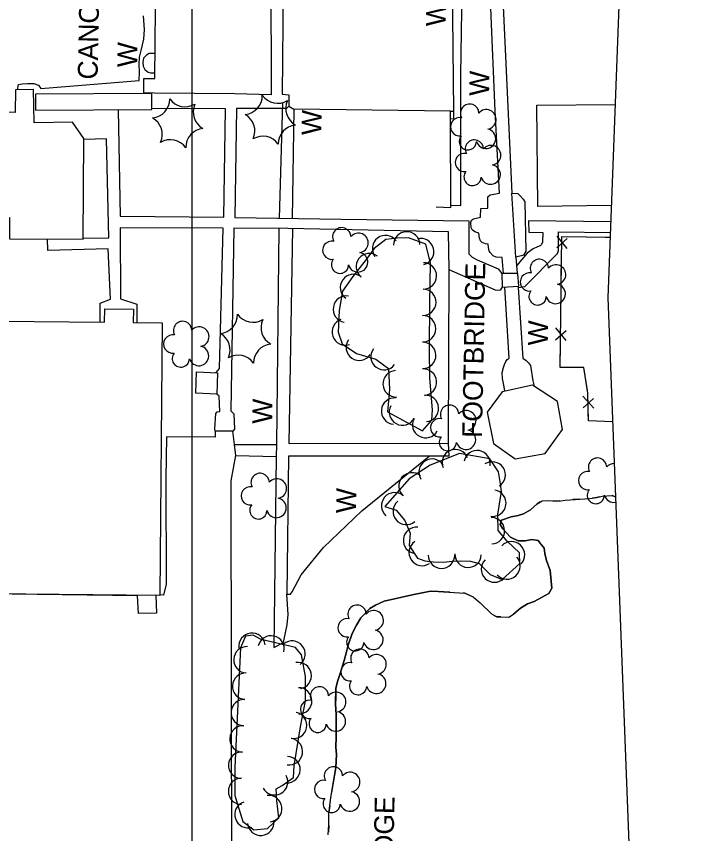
# Model space of a CAD drawing. Extents: x 591954 to 597000, y 198576 to 213500.
# Drawn here: x 594446.8 to 594650.3, y 209666.9 to 209914.5 of the extents above; entities that cross this region are included whole.
import ezdxf

# ---------------------------------------------------------------- set-up
doc = ezdxf.new("R2010")
doc.units = 0
for name, color, linetype in [('Level 10', 7, 'Continuous'), ('Level 12', 7, 'Continuous'), ('Level 15', 7, 'Continuous'), ('Level 17', 7, 'Continuous'), ('Level 18', 7, 'Continuous'), ('Level 19', 7, 'Continuous'), ('Level 4', 7, 'Continuous')]:
    doc.layers.add(name, color=color, linetype=linetype)

msp = doc.modelspace()

# ---------------------------------------------------------------- linework, layer by layer
at = {"layer": 'Level 10'}
for p, q in [((594500, 209500), (594500, 210500)), ((594500, 208500), (594500, 210000))]:
    msp.add_line(p, q, dxfattribs=at)
at = {"layer": 'Level 12'}
for points in [[(594513.34, 209927.19), (594523.83, 209927.08), (594523.89, 209890.77), (594512.94, 209890.99), (594488.59, 209891.26), (594485.34, 209891.3), (594485.39, 209895.68), (594488.65, 209895.65), (594489.01, 209927.47), (594513.34, 209927.19)], [(594446.43, 209885.39), (594405.52, 209885.59), (594405.47, 209874.71), (594398.11, 209874.75), (594398.08, 209869.64), (594405.35, 209869.61), (594405.27, 209853.82), (594444.7, 209853.63), (594444.67, 209847.16), (594466.99, 209847.05), (594467.15, 209877.52), (594463.75, 209882.48), (594452.14, 209882.29), (594451.97, 209892.38), (594446.47, 209892.29), (594446.43, 209885.39)], [(594452.58, 209886.09), (594487.76, 209886.31), (594487.73, 209891.11), (594452.55, 209890.89), (594452.58, 209886.09)], [(594604.29, 209887.62), (594628.02, 209887.85)], [(594626.86, 209857.17), (594604.58, 209856.96), (594604.29, 209887.62)], [(594430.68, 209822.33), (594473.47, 209821.92), (594473.51, 209825.91), (594482.17, 209825.83), (594482.13, 209821.78), (594490.93, 209821.69), (594490.14, 209739.13), (594429.23, 209739.72), (594429.13, 209729.13), (594406.41, 209729.35), (594406.8, 209769.83), (594396.44, 209769.93), (594396.53, 209779.02), (594382.62, 209779.15), (594382.6, 209777.29), (594353.34, 209777.57), (594353.77, 209822.05), (594381.3, 209821.78), (594381.34, 209825.57), (594391.73, 209825.47), (594391.68, 209819.76), (594430.65, 209819.38), (594430.68, 209822.33)], [(594507.4, 209800.08), (594501.06, 209800.34), (594501.32, 209806.82), (594507.66, 209806.57), (594507.4, 209800.08)], [(594610.57, 209797.83), (594602.96, 209802.78), (594593.79, 209800.77), (594589.26, 209794.58), (594591.22, 209785.09), (594597.77, 209780.48), (594606.88, 209782.05), (594612.06, 209789.37), (594610.57, 209797.83)]]:
    msp.add_lwpolyline(points, dxfattribs=at)
at = {"layer": 'Level 15'}
for p, q in [((594613.48, 209844.22), (594610.44, 209847.96)), ((594610.33, 209844.42), (594613.53, 209847.18)), ((594610.01, 209816.57), (594613.21, 209819.33)), ((594613.25, 209816.36), (594610.05, 209820.11)), ((594621.61, 209795.81), (594618.29, 209799.46)), ((594618.37, 209795.91), (594621.48, 209798.77))]:
    msp.add_line(p, q, dxfattribs=at)
for points in [[(594578.94, 209964.24), (594578.71, 209950.63), (594578.74, 209914.58), (594579.05, 209885.83), (594579.07, 209883.45), (594578.14, 209883.38)], [(594578.32, 209857.27), (594581.33, 209857.26), (594581.35, 209896.69), (594581.71, 209922.93), (594582.27, 209922.92), (594582.35, 209925.44), (594581.68, 209925.45), (594581.94, 209954.49), (594581.79, 209961.46)], [(594592.06, 209961.24), (594593.07, 209939.03), (594594.54, 209908.88), (594596.73, 209860.97), (594598.58, 209860.87), (594599.32, 209860.16), (594600.21, 209859.16), (594600.67, 209858.32), (594600.95, 209843.42), (594600.24, 209842.15), (594599.6, 209841.98), (594597.98, 209841.53), (594598.35, 209836.66)], [(594594.25, 209836.58), (594593.79, 209841.49), (594592.04, 209841.52), (594591.15, 209841.92), (594590.15, 209842.94), (594589.86, 209843.44), (594589.68, 209844.46), (594589.6, 209845.48), (594588.81, 209845.56), (594587.8, 209846.05), (594587.29, 209846.56), (594586.99, 209847.36), (594586.78, 209848.84), (594585.52, 209849.27), (594584.7, 209849.82), (594584.39, 209850.5), (594584.33, 209852.11), (594584.56, 209852.73), (594585.15, 209853.15), (594587.29, 209853.7), (594587.32, 209856.34), (594589.49, 209856.42), (594589.53, 209859.83), (594590.18, 209860.49), (594592.98, 209860.95), (594591.67, 209885.92), (594590.39, 209916.99)], [(594488.73, 209903.23), (594487.75, 209903.25), (594486.96, 209903.21), (594486.11, 209902.75), (594485.25, 209901.82), (594485.08, 209900.58), (594485.16, 209899.39), (594485.6, 209898.43), (594486.67, 209897.64), (594487.36, 209897.4), (594488.67, 209897.38)], [(594526.46, 209853.31), (594527.42, 209888.33)], [(594573.86, 209856.78), (594578.32, 209856.65), (594578.14, 209883.38), (594578.14, 209885.79), (594530.72, 209886.42), (594530.25, 209853.24)], [(594597.98, 209841.53), (594596.73, 209860.99)], [(594526.23, 209850.26), (594525.49, 209784.84), (594525.41, 209781.18), (594524.68, 209723.37)], [(594530.35, 209850.21), (594529.27, 209785.08), (594577.56, 209785.26), (594577.76, 209837.75)], [(594627.25, 209791.68), (594619.95, 209791.96), (594619.77, 209800.38), (594618.58, 209808.11), (594611.42, 209808.11), (594611.86, 209847.8), (594626.5, 209847.65)], [(594613.72, 209847.78), (594625.04, 209847.67)], [(594625.04, 209847.67), (594626.5, 209847.65)], [(594611.7, 209833.12), (594611.81, 209843.08)], [(594593.86, 209832.47), (594598.86, 209832.76), (594598.58, 209836.66), (594593.73, 209836.57), (594593.86, 209832.47)], [(594594.25, 209836.58), (594594.25, 209836.58)], [(594611.57, 209821.8), (594611.7, 209833.12)], [(594594.65, 209800.96), (594594.39, 209802.24), (594593.96, 209804.81), (594593.85, 209806.68), (594594.22, 209808.12), (594594.5, 209809.09), (594594.93, 209809.92), (594595.29, 209810.57), (594595.93, 209810.98), (594594.62, 209832.51)], [(594598.67, 209832.75), (594598.67, 209832.75)], [(594598.67, 209832.75), (594598.68, 209832.38), (594600.05, 209810.98), (594601.14, 209810.28), (594601.78, 209809.59), (594602.36, 209808.71), (594603.14, 209804.11), (594603.47, 209802.45)], [(594614.27, 209808.11), (594611.42, 209808.11), (594611.5, 209815.22)], [(594619.65, 209801.18), (594618.58, 209808.11), (594614.27, 209808.11)], [(594627.25, 209791.68), (594619.95, 209791.96), (594619.89, 209794.61)], [(594577.82, 209781.31), (594529.13, 209781.3), (594528.67, 209739.51), (594529.21, 209739.44), (594529.74, 209739.51), (594530.24, 209740.19), (594533, 209745.34), (594539.76, 209753.6), (594551.31, 209764.71), (594571.69, 209781.31)]]:
    msp.add_lwpolyline(points, dxfattribs=at)
at = {"layer": 'Level 17'}
for points in [[(594523.83, 209922.94), (594527.55, 209922.94), (594527.2, 209890.89), (594529.26, 209890.69), (594529.27, 209887.26), (594528.58, 209886.59), (594513.39, 209886.6), (594512.87, 209853.61), (594545.09, 209853.1), (594583.73, 209852.6), (594583.76, 209842.55), (594584.73, 209841.59), (594586.27, 209840.78), (594592.65, 209838.03), (594593.73, 209836.57)], [(594447.05, 209892.3), (594447.44, 209893.88), (594448.5, 209894.09), (594450.13, 209894.12), (594452.04, 209894.15), (594453.42, 209893.7), (594454.15, 209892.64), (594483.9, 209895.05), (594484, 209897.67), (594483.92, 209899.9), (594484.06, 209902.17), (594484.53, 209904.13), (594485.39, 209907.55), (594485.52, 209910.52), (594485.2, 209914.62)], [(594477.56, 209886.24), (594478.18, 209853.99), (594509.53, 209853.7), (594510.1, 209886.46), (594487.76, 209886.61)], [(594529.27, 209887.26), (594530.72, 209886.42)], [(594578.14, 209885.79), (594579.05, 209885.83)], [(594467, 209847.35), (594474.76, 209847.39), (594474.07, 209877.38), (594467.14, 209877.18)], [(594507.26, 209806.58), (594508.3, 209807.82), (594509.33, 209850.38), (594478.22, 209850.47), (594478.31, 209828.99), (594483.24, 209827.36)], [(594593.86, 209832.47), (594593.2, 209831.6), (594592.39, 209831.46), (594591.76, 209831.57), (594577.76, 209837.75), (594577.62, 209849.27), (594528.95, 209850.24), (594512.56, 209850.37), (594511.66, 209795.05), (594512.55, 209794.11), (594512.79, 209789.48), (594512.27, 209788.82)], [(594626.68, 209852.3), (594601.81, 209852.55), (594601.86, 209849.14), (594606.09, 209849.02), (594606.07, 209846.06), (594605.77, 209845.39), (594605.3, 209845.04), (594604.5, 209844.74), (594603.2, 209844.05), (594601.4, 209842.77), (594598.18, 209838.91)], [(594598.68, 209832.38), (594600.65, 209832.66), (594610.59, 209842.68), (594610.88, 209843.58), (594610.88, 209849.21), (594626.55, 209848.99)], [(594472.15, 209821.93), (594472.08, 209827.66), (594475.22, 209828.81), (594474.59, 209844.09), (594456.3, 209843.57), (594456.19, 209847.1)], [(594483.24, 209827.36), (594483.23, 209821.77)], [(594506.99, 209788.84), (594506.86, 209789.56), (594507.1, 209794.17), (594507.52, 209794.68), (594508.33, 209794.79), (594508.18, 209799.45), (594507.4, 209800.08)], [(594506.99, 209788.84), (594506.89, 209787.02), (594492.24, 209787.1), (594491.96, 209774.44), (594492.07, 209742.52), (594491.3, 209739.17), (594490.14, 209739.24)], [(594512.27, 209788.82), (594506.99, 209788.84)], [(594512.82, 209784.83), (594512.27, 209788.82)], [(594512.82, 209784.83), (594525.49, 209784.84)], [(594513.15, 209781.47), (594512.82, 209784.83)], [(594577.82, 209781.31), (594577.56, 209785.26)], [(594501.42, 209653.42), (594511.94, 209653.35), (594511.78, 209773.77), (594513.15, 209781.47)], [(594513.15, 209781.47), (594525.41, 209781.18)], [(594489.01, 209739.14), (594489.14, 209733.7), (594483.68, 209733.67), (594483.47, 209738.93), (594430.19, 209739.65), (594430.17, 209729.62), (594429.14, 209729.63)], [(594524.68, 209723.37), (594527.64, 209724.87), (594527.87, 209725.86), (594528.76, 209730.19), (594529.05, 209733.36), (594528.67, 209739.51)]]:
    msp.add_lwpolyline(points, dxfattribs=at)
at = {"layer": 'Level 18'}
for points in [[(594559.13, 209794.72), (594569.67, 209788.98), (594572.5, 209792.2), (594572.73, 209795.29), (594571.97, 209804.96), (594571.83, 209813.73), (594571.89, 209827.73), (594572.15, 209839.78), (594570.75, 209845.5), (594565.43, 209847.39), (594562.07, 209847.32), (594558.64, 209846.87), (594555.04, 209844.17), (594552.68, 209840.89), (594548.64, 209835.74), (594545.49, 209831.3), (594544.47, 209825.46), (594544.14, 209818.82), (594545.34, 209815.33), (594549.68, 209812.37), (594555.55, 209810.69), (594559.42, 209807.8), (594559.73, 209801.47), (594559.13, 209794.72)], [(594593.31, 209772.86), (594592.73, 209776.52), (594590.11, 209780.45), (594580.93, 209782.1), (594572, 209778.54), (594565.62, 209774.45), (594558.29, 209766.02), (594561.75, 209764.93), (594564.33, 209761.83), (594566.01, 209758), (594565.63, 209754.21)], [(594565.63, 209754.21), (594568.24, 209750.41), (594570.43, 209749.63), (594572.92, 209749.23), (594576.05, 209749.2), (594578.65, 209749.47), (594581.07, 209749.58), (594584.2, 209749.46), (594586.85, 209748.74), (594590.23, 209745.41), (594593.8, 209743.9), (594599.21, 209748.74), (594599.06, 209752), (594595.34, 209755.55), (594592.66, 209758.74), (594592.56, 209763.63), (594593.67, 209770.59), (594593.31, 209772.86)], [(594530.84, 209687.5), (594532.74, 209699.3), (594534.32, 209707.18), (594534.24, 209714.59), (594533.08, 209721.07), (594531.24, 209723.36), (594520.86, 209725.75), (594518.47, 209727.03), (594516.1, 209726.73), (594514.64, 209723.25), (594512.85, 209687.09), (594512.85, 209678.46), (594515.33, 209670.6), (594518.63, 209668.1), (594522.81, 209668.49), (594526.2, 209671.78), (594525.62, 209676.98), (594525.4, 209680.51), (594527.22, 209681.49), (594530.69, 209683.95), (594530.84, 209687.5)]]:
    msp.add_lwpolyline(points, dxfattribs=at)
for centre, radius, start, end in [((594515.49, 209890.49), 5.72, 275.2113, 0.9762), ((594525.89, 209893.89), 5.72, 215.2113, 300.9762), ((594487.47, 209889.44), 5.72, 275.2113, 0.9762), ((594497.87, 209892.84), 5.72, 215.2113, 300.9762), ((594506.02, 209885.53), 5.72, 155.2113, 240.9762), ((594534.03, 209886.58), 5.72, 155.2113, 240.9762), ((594583.98, 209885.15), 2.78, 1.3946, 209.1675), ((594513.23, 209879.79), 5.72, 335.2113, 60.9762), ((594589.02, 209883.29), 2.97, 278.4237, 139.6575), ((594485.21, 209878.73), 5.72, 335.2113, 60.9762), ((594580.98, 209881.07), 2.78, 78.0716, 279.0826), ((594503.76, 209874.82), 5.72, 95.2113, 180.9762), ((594531.78, 209875.88), 5.72, 95.2113, 180.9762), ((594588.91, 209877.44), 2.97, 196.0745, 79.0477), ((594521.38, 209872.48), 5.72, 35.2113, 120.9762), ((594583.44, 209876.67), 2.61, 140.7797, 358.7123), ((594493.36, 209871.43), 5.72, 35.2113, 120.9762), ((594585.41, 209874.31), 2.78, 1.3946, 209.1675), ((594590.46, 209872.45), 2.97, 278.4237, 139.6575), ((594582.41, 209870.24), 2.78, 78.0716, 279.0826), ((594584.87, 209865.84), 2.61, 140.7797, 358.7123), ((594590.34, 209866.6), 2.97, 196.0745, 79.0477), ((594545.26, 209847.74), 2.78, 1.3946, 209.1675), ((594550.31, 209845.88), 2.97, 278.4237, 139.6575), ((594542.26, 209843.66), 2.78, 78.0716, 279.0826), ((594550.19, 209840.03), 2.97, 196.0745, 79.0477), ((594544.73, 209839.26), 2.61, 140.7797, 358.7123), ((594605.08, 209838.15), 2.78, 1.3946, 209.1675), ((594569.97, 209835.9), 4, 268.8003, 88.785), ((594610.12, 209836.29), 2.97, 278.4237, 139.6575), ((594602.08, 209834.07), 2.78, 78.0716, 279.0826), ((594610.01, 209830.44), 2.97, 196.0745, 79.0477), ((594569.8, 209827.9), 4, 268.8003, 88.785), ((594604.54, 209829.67), 2.61, 140.7797, 358.7123), ((594508, 209824.16), 5.72, 275.2113, 0.9762), ((594518.4, 209827.56), 5.72, 215.2113, 300.9762), ((594497.09, 209819.35), 2.78, 1.3946, 209.1675), ((594502.13, 209817.49), 2.97, 278.4237, 139.6575), ((594526.54, 209820.25), 5.72, 155.2113, 240.9762), ((594494.09, 209815.27), 2.78, 78.0716, 279.0826), ((594505.74, 209813.45), 5.72, 335.2113, 60.9762), ((594502.02, 209811.64), 2.97, 196.0745, 79.0477), ((594524.29, 209809.54), 5.72, 95.2113, 180.9762), ((594496.55, 209810.87), 2.61, 140.7797, 358.7123), ((594513.89, 209806.15), 5.72, 35.2113, 120.9762), ((594577.91, 209794), 2.78, 1.3946, 209.1675), ((594582.95, 209792.14), 2.97, 278.4237, 139.6575), ((594574.91, 209789.92), 2.78, 78.0716, 279.0826), ((594582.84, 209786.29), 2.97, 196.0745, 79.0477), ((594577.37, 209785.52), 2.61, 140.7797, 358.7123), ((594622.7, 209777.97), 2.78, 1.3946, 209.1675), ((594627.75, 209776.11), 2.97, 90.25, 139.6575), ((594520.56, 209773.33), 2.78, 1.3946, 209.1675), ((594619.7, 209773.89), 2.78, 78.0716, 279.0826), ((594525.6, 209771.47), 2.97, 278.4237, 139.6575), ((594517.56, 209769.25), 2.78, 78.0716, 279.0826), ((594622.17, 209769.49), 2.61, 140.7797, 358.7123), ((594525.49, 209765.62), 2.97, 196.0745, 79.0477), ((594627.63, 209770.26), 2.97, 196.0745, 280.6417), ((594520.02, 209764.85), 2.61, 140.7797, 358.7123), ((594549.88, 209733.4), 2.78, 1.3946, 209.1675), ((594554.93, 209731.54), 2.97, 278.4237, 139.6575), ((594546.88, 209729.32), 2.78, 78.0716, 279.0826), ((594549.35, 209724.92), 2.61, 140.7797, 358.7123), ((594554.82, 209725.69), 2.97, 196.0745, 79.0477), ((594516.55, 209719.61), 4, 87.18, 267.1646), ((594550.74, 209720.09), 2.78, 1.3946, 209.1675), ((594555.78, 209718.23), 2.97, 278.4237, 139.6575), ((594547.74, 209716.01), 2.78, 78.0716, 279.0826), ((594516.16, 209711.62), 4, 87.18, 267.1646), ((594555.67, 209712.38), 2.97, 196.0745, 79.0477), ((594550.2, 209711.61), 2.61, 140.7797, 358.7123), ((594538.52, 209708.66), 2.78, 1.3946, 209.1675), ((594543.56, 209706.81), 2.97, 278.4237, 139.6575), ((594515.77, 209703.63), 4, 87.18, 267.1646), ((594535.52, 209704.59), 2.78, 78.0716, 279.0826), ((594537.98, 209700.19), 2.61, 140.7797, 358.7123), ((594543.45, 209700.95), 2.97, 196.0745, 79.0477), ((594515.37, 209695.64), 4, 87.18, 267.1646), ((594514.98, 209687.65), 4, 87.18, 267.1646), ((594542.75, 209684.42), 2.78, 1.3946, 209.1675), ((594547.8, 209682.56), 2.97, 278.4237, 139.6575), ((594539.75, 209680.34), 2.78, 78.0716, 279.0826), ((594547.69, 209676.71), 2.97, 196.0745, 79.0477), ((594542.22, 209675.95), 2.61, 140.7797, 358.7123)]:
    msp.add_arc(centre, radius, start, end, dxfattribs=at)
for centre, major_axis, ratio, start_param, end_param in [((594558.52, 209844.16), (-1.72, 3.61), 0.999936, 4.910446, 8.051772), ((594564.93, 209845.28), (0.74, 3.93), 0.999884, 4.919601, 8.060927), ((594569.15, 209843.24), (-2.62, -3.03), 0.999998, 0.953194, 4.094519), ((594553.6, 209838.67), (3.52, -1.91), 0.999957, 1.40175, 4.543075), ((594548.83, 209832.39), (-1.17, 3.83), 0.999997, 5.37215, 8.513475), ((594546.66, 209825.83), (3.95, -0.6), 0.999994, 1.548863, 4.690188), ((594569.76, 209819.87), (-3.81, -1.21), 0.999999, 1.259244, 4.40057), ((594546.32, 209818.92), (-3.83, -1.15), 0.999279, 4.751186, 7.892511), ((594550.58, 209814.29), (-3.31, 2.25), 0.999996, 0, 3.141325), ((594569.77, 209811.83), (-3.88, -0.96), 0.999997, 1.344, 4.485325), ((594558.05, 209811.44), (-2.71, -2.94), 0.999635, 4.816268, 7.957593), ((594561.74, 209803.19), (-4, 0.12), 0.999969, 4.791787, 7.933113), ((594569.97, 209803.7), (-3.67, -1.6), 0.999998, 1.23666, 4.377985), ((594561.25, 209794.93), (-3.96, 0.53), 0.99999, 4.75606, 7.897385), ((594570.59, 209795.73), (-3.67, -1.6), 0.999998, 1.23666, 4.377985), ((594563.64, 209794.65), (1.52, 3.7), 0.999618, 1.462752, 4.604077), ((594570.66, 209790.83), (1.52, 3.7), 0.999618, 1.462752, 4.604077), ((594579.63, 209779.33), (1.94, 3.5), 0.999988, 5.59866, 8.739985), ((594586.23, 209779.02), (0.72, 3.93), 0.999814, 4.716095, 7.85742), ((594572.61, 209776.44), (2.69, 2.96), 0.999987, 6.019813, 9.161139), ((594590.82, 209775.6), (3.91, 0.82), 0.999906, 5.093114, 8.23444), ((594566.52, 209772.29), (3.03, 2.61), 0.999981, 0.144757, 3.286082), ((594590.99, 209767.06), (-3.62, -1.71), 0.99971, 0.971122, 4.112447), ((594561.27, 209766.25), (3.03, 2.61), 0.999981, 0.144757, 3.286082), ((594564.79, 209764.55), (-3.96, -0.59), 0.999962, 5.258005, 8.39933), ((594590.57, 209758.73), (-2.67, -2.98), 0.999888, 0.752339, 3.893664), ((594567.89, 209755.78), (1.75, 3.59), 0.999971, 0.354792, 3.496117), ((594569.61, 209752.11), (3.29, 2.28), 0.997293, 1.567223, 4.708548), ((594596.64, 209751.41), (1.28, -3.79), 0.999991, 0.483669, 3.624994), ((594575.47, 209751.3), (-4, 0.04), 0.999876, 0.000134, 3.141459), ((594583.52, 209751.58), (-3.75, -1.38), 0.999861, 5.890099, 9.031424), ((594591.51, 209747.09), (-3.9, 0.89), 0.999992, 5.728183, 8.869508), ((594595.28, 209748.04), (-3.33, -2.22), 0.99981, 0.141964, 3.283289), ((594518.11, 209723.67), (1.23, -3.81), 0.999964, 1.386246, 4.527571), ((594523.88, 209722.9), (1.21, 3.81), 0.999856, 4.793422, 7.934747), ((594530.19, 209721.33), (3.16, 2.45), 0.99942, 4.7293, 7.870626), ((594532.07, 209714.81), (-3.92, -0.81), 0.999971, 1.543141, 4.684466), ((594532.23, 209707.16), (4, -0.06), 0.999846, 4.739263, 7.880588), ((594530.7, 209699.75), (3.82, -1.19), 0.999972, 4.815696, 7.957021), ((594529.41, 209691.78), (3.93, -0.75), 0.999706, 4.74221, 7.883535), ((594528.7, 209686.33), (-4, 0.08), 0.999747, 1.546442, 4.687767), ((594524.95, 209682.65), (1.66, -3.64), 0.999706, 4.777119, 7.918445), ((594514.95, 209679.76), (3.92, 0.82), 0.999997, 1.364418, 4.505743), ((594523.16, 209674.53), (-3.97, -0.51), 0.999817, 1.554495, 4.695821), ((594516.87, 209672.7), (3.81, 1.21), 0.999953, 1.570339, 4.711664), ((594520.74, 209670.4), (-1.87, -3.54), 0.999996, 5.291068, 8.432393)]:
    msp.add_ellipse(centre, major_axis=major_axis, ratio=ratio, start_param=start_param, end_param=end_param, dxfattribs=at)
at = {"layer": 'Level 19'}
for points in [[(594551.04, 209732.28), (594553.77, 209735.14), (594555.43, 209736.11), (594558.12, 209737.34), (594567.08, 209739.43), (594572.09, 209740.37), (594574.5, 209740.26), (594582.48, 209739.78), (594585.03, 209738.72), (594587.15, 209736.88), (594590.63, 209733.51), (594592.16, 209732.58), (594595.81, 209732.54), (594597.28, 209733.43), (594599.41, 209735.22), (594601.54, 209736.56), (594603.53, 209737.24), (594607.94, 209739.71), (594608.82, 209741.34), (594608.37, 209746.64), (594607.29, 209749.65), (594606.72, 209751.81), (594606.53, 209753.41), (594604.71, 209755.75), (594602.78, 209756.05), (594600.79, 209755.68), (594598.67, 209755.6), (594596.35, 209756.72), (594594.06, 209759.24), (594593.22, 209760.63), (594593.65, 209761.93), (594596.52, 209762.86), (594598.65, 209763.27), (594600.33, 209763.8), (594602.36, 209765.06), (594604.4, 209766.89), (594605.94, 209767.78), (594607.85, 209767.9), (594610.31, 209767.64), (594611.59, 209767.77), (594612.91, 209767.96), (594620.4, 209768.46), (594622.51, 209768.77), (594624.07, 209769.22), (594627, 209769.39), (594628.12, 209768.99)], [(594623.17, 209768.96), (594622.51, 209768.77), (594621.21, 209768.58)], [(594628.12, 209768.99), (594627.12, 209769.35)], [(594628.12, 209768.99), (594628.12, 209768.99)], [(594628.12, 209768.99), (594628.12, 209768.99)], [(594605.36, 209767.45), (594604.4, 209766.89), (594602.36, 209765.06), (594600.33, 209763.8), (594598.65, 209763.27), (594596.52, 209762.86), (594593.65, 209761.93), (594593.22, 209760.63), (594594.06, 209759.24), (594596.35, 209756.72), (594598.67, 209755.6), (594600.79, 209755.68), (594602.78, 209756.05), (594604.71, 209755.75), (594605.16, 209755.17)], [(594611.25, 209767.74), (594610.31, 209767.64), (594609.26, 209767.75)], [(594617.23, 209768.25), (594615.23, 209768.11)], [(594605.16, 209755.17), (594606.53, 209753.41), (594606.72, 209751.81), (594607.29, 209749.65), (594608.37, 209746.64), (594608.82, 209741.34), (594607.94, 209739.71), (594603.53, 209737.24), (594601.54, 209736.56), (594599.41, 209735.22), (594597.28, 209733.43), (594597.19, 209733.38)], [(594577.95, 209740.05), (594574.5, 209740.26), (594572.09, 209740.37), (594567.08, 209739.43), (594558.12, 209737.34), (594555.43, 209736.11), (594553.77, 209735.14), (594551.04, 209732.28)], [(594583.83, 209739.22), (594582.48, 209739.78), (594581.94, 209739.81)], [(594588.51, 209735.56), (594587.15, 209736.88), (594587.07, 209736.95)], [(594541.17, 209666.63), (594541.33, 209669.62), (594541.35, 209673.03), (594541.91, 209677.84), (594543.45, 209686.95), (594543.68, 209690.95), (594543.52, 209693.13), (594543.62, 209696.31), (594543.58, 209703.05), (594543.38, 209706.15), (594543.48, 209710.86), (594543.95, 209713.03), (594544.79, 209715.5), (594546.02, 209719.41), (594546.66, 209722.05), (594547.24, 209724.04), (594548.45, 209727.55), (594549.68, 209730.11), (594551.04, 209732.28)], [(594551.04, 209732.28), (594549.68, 209730.11), (594548.45, 209727.55), (594547.24, 209724.04), (594546.66, 209722.05), (594546.02, 209719.41), (594544.79, 209715.5), (594543.95, 209713.03), (594543.48, 209710.86), (594543.42, 209708.23)], [(594593.42, 209732.57), (594592.16, 209732.58), (594591.53, 209732.96)], [(594543.42, 209708.23), (594543.38, 209706.15), (594543.58, 209703.05), (594543.62, 209696.31), (594543.52, 209693.13), (594543.68, 209690.95), (594543.45, 209686.95), (594542.17, 209679.36)], [(594541.63, 209675.4), (594541.4, 209673.41)], [(594541.32, 209669.41), (594541.21, 209667.42)]]:
    msp.add_lwpolyline(points, dxfattribs=at)
at = {"layer": 'Level 4'}
msp.add_lwpolyline([(594650.28, 210487.07), (594646.64, 210381.3), (594625.81, 209829.22), (594635.47, 209577.53)], dxfattribs=at)

# ---------------------------------------------------------------- texts
at = {"layer": 'Level 12'}
msp.add_text('CANOPY', height=6, rotation=88.8928, dxfattribs=at).set_placement((594471.33, 209895.33))
at = {"layer": 'Level 15'}
for s, rotation, p in [('W', 89.144, (594576.73, 209911.46)), ('W', 89.144, (594483.3, 209899.06)), ('W', 89.144, (594589.86, 209890.38)), ('W', 89.144, (594539.09, 209878.51)), ('FOOTBRIDGE', 88.8928, (594587.72, 209786.79)), ('W', 89.144, (594607.62, 209814.77)), ('W', 89.144, (594524.18, 209791.04)), ('W', 89.144, (594549.56, 209763.99)), ('FOOTBRIDGE', 88.8928, (594560.24, 209625.15))]:
    msp.add_text(s, height=6, rotation=rotation, dxfattribs=at).set_placement(p)

doc.saveas('drawing.dxf')
